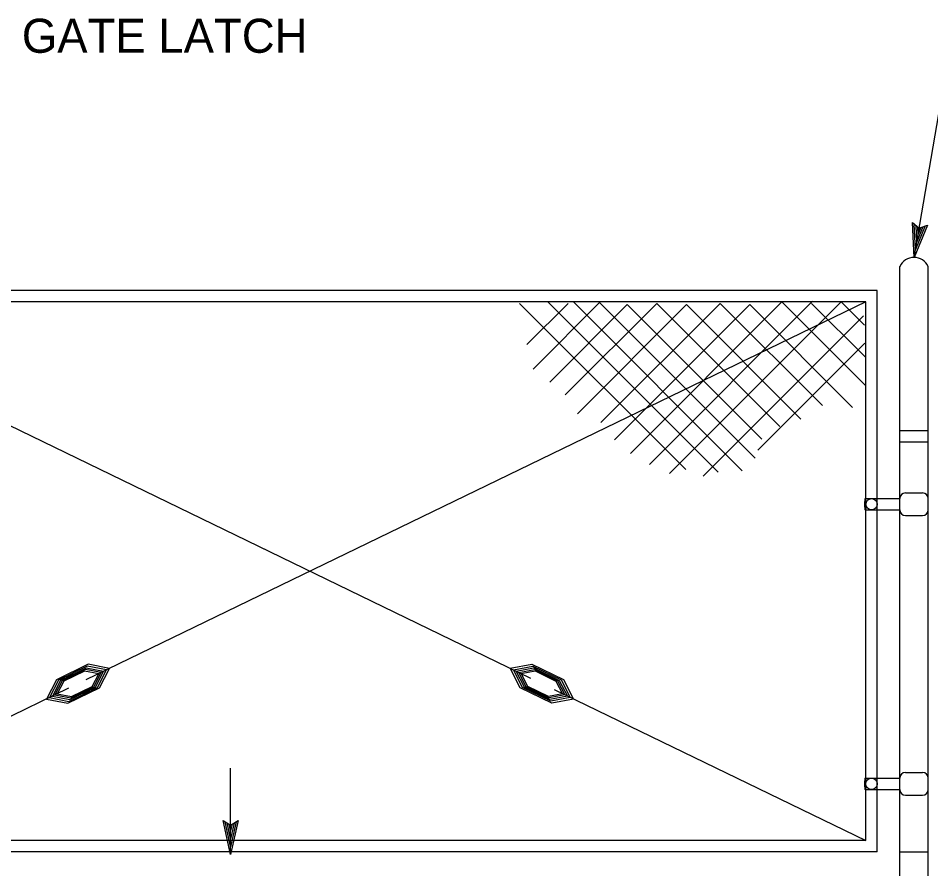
# Model space of a CAD drawing. Extents: x -121875 to -117742, y -103854 to -101122.
# Drawn here: x -120907.1 to -120746.2, y -102378.2 to -102228.3 of the extents above; entities that cross this region are included whole.
import ezdxf

# ---------------------------------------------------------------- set-up
doc = ezdxf.new("R2010")
doc.units = 0
for name, color, linetype in [('G-MARK', 7, 'Continuous'), ('G-TEXT', 7, 'Continuous'), ('Misc CnstDet(22)', 7, 'Continuous'), ('Nongeo Data(60)', 7, 'Continuous')]:
    doc.layers.add(name, color=color, linetype=linetype)

msp = doc.modelspace()

# ---------------------------------------------------------------- linework, layer by layer
at = {"layer": 'G-MARK'}
for p, q in [((-120749.16, -102270.41), (-120749.44, -102264.27)), ((-120749.44, -102264.27), (-120749.44, -102264.27)), ((-120749.44, -102264.27), (-120748.27, -102265.28)), ((-120746.81, -102264.72), (-120749.16, -102270.41)), ((-120748.92, -102269.03), (-120749.13, -102264.56)), ((-120747.2, -102264.88), (-120748.92, -102269.05)), ((-120748.68, -102267.68), (-120748.81, -102264.79)), ((-120747.59, -102265.04), (-120748.68, -102267.68)), ((-120748.44, -102266.32), (-120748.5, -102265.09)), ((-120747.96, -102265.16), (-120748.44, -102266.32)), ((-120748.27, -102265.28), (-120746.81, -102264.72)), ((-120746.81, -102264.72), (-120746.81, -102264.72)), ((-120749.16, -102270.41), (-120749.16, -102270.41)), ((-120869.67, -102375.7), (-120869.67, -102360.47))]:
    msp.add_line(p, q, dxfattribs=at)
msp.add_lwpolyline([(-120749.16, -102270.41), (-120744.76, -102245.1), (-120744.76, -102245.1)], dxfattribs=at)
at = {"layer": 'G-TEXT'}
for p, q in [((-120869.67, -102375.7), (-120871, -102369.7)), ((-120871, -102369.7), (-120871, -102369.7)), ((-120871, -102369.7), (-120869.67, -102370.5)), ((-120869.67, -102374.31), (-120870.64, -102369.93)), ((-120869.67, -102372.94), (-120870.29, -102370.11)), ((-120869.67, -102371.55), (-120869.93, -102370.35)), ((-120869.67, -102370.5), (-120868.33, -102369.7)), ((-120868.33, -102369.7), (-120869.67, -102375.7)), ((-120868.68, -102369.92), (-120869.67, -102374.32)), ((-120869.04, -102370.15), (-120869.67, -102372.94)), ((-120869.39, -102370.33), (-120869.67, -102371.55)), ((-120868.33, -102369.7), (-120868.33, -102369.7)), ((-120869.67, -102375.7), (-120869.67, -102375.7))]:
    msp.add_line(p, q, dxfattribs=at)
at = {"layer": 'Nongeo Data(60)'}
for p, q in [((-120751.66, -102358.97), (-120751.66, -102272.05)), ((-120746.66, -102358.97), (-120746.66, -102272.05)), ((-120755.66, -102276.24), (-120955.66, -102276.24)), ((-120755.66, -102301.58), (-120755.66, -102276.24)), ((-120757.66, -102278.24), (-120953.66, -102278.24)), ((-120953.66, -102278.24), (-120816.78, -102344.59)), ((-120757.66, -102278.24), (-120895.22, -102344.92)), ((-120789.41, -102307.83), (-120818.73, -102278.52)), ((-120817.42, -102285.75), (-120810.18, -102278.52)), ((-120816.35, -102290.14), (-120804.49, -102278.28)), ((-120783.72, -102308.3), (-120813.74, -102278.28)), ((-120813.39, -102292.4), (-120799.74, -102278.75)), ((-120810.66, -102294.65), (-120794.52, -102278.52)), ((-120779.45, -102308.06), (-120809.23, -102278.28)), ((-120808.52, -102297.98), (-120789.3, -102278.75)), ((-120777.19, -102305.81), (-120804.72, -102278.28)), ((-120804.37, -102299.52), (-120783.36, -102278.52)), ((-120801.99, -102302.6), (-120778.14, -102278.75)), ((-120776.01, -102302.49), (-120799.74, -102278.75)), ((-120799.15, -102304.98), (-120772.45, -102278.28)), ((-120795.81, -102306.91), (-120767.06, -102278.16)), ((-120772.8, -102300.23), (-120794.52, -102278.52)), ((-120792.26, -102308.54), (-120762, -102278.28)), ((-120769.12, -102298.93), (-120789.3, -102278.75)), ((-120765.33, -102296.55), (-120783.36, -102278.52)), ((-120759.99, -102296.91), (-120778.14, -102278.75)), ((-120757.79, -102292.93), (-120772.45, -102278.28)), ((-120757.66, -102288.08), (-120767.22, -102278.52)), ((-120757.9, -102282.38), (-120762, -102278.28)), ((-120757.66, -102301.21), (-120757.66, -102278.24)), ((-120786.33, -102309.01), (-120758.05, -102280.74)), ((-120776.72, -102304.38), (-120757.86, -102285.53)), ((-120757.66, -102373.24), (-120757.66, -102301.21)), ((-120751.66, -102300.95), (-120746.66, -102300.95)), ((-120755.66, -102375.24), (-120755.66, -102301.58)), ((-120751.66, -102302.95), (-120746.66, -102302.95)), ((-120755.66, -102312.95), (-120755.66, -102309.67)), ((-120751.66, -102311.93), (-120751.66, -102309.67)), ((-120746.66, -102311.94), (-120746.66, -102309.67)), ((-120751.66, -102317.59), (-120751.66, -102311.93)), ((-120750.66, -102311.95), (-120747.66, -102311.95)), ((-120746.66, -102317.59), (-120746.66, -102311.9)), ((-120757.78, -102312.95), (-120751.66, -102312.95)), ((-120751.66, -102314.95), (-120751.66, -102312.95)), ((-120746.66, -102314.95), (-120746.66, -102312.95)), ((-120757.78, -102314.95), (-120751.66, -102314.95)), ((-120755.66, -102317.59), (-120755.66, -102314.95)), ((-120750.66, -102315.95), (-120747.66, -102315.95)), ((-120894.81, -102342.16), (-120900.38, -102344.87)), ((-120894.99, -102342.51), (-120900, -102344.94)), ((-120895.15, -102342.82), (-120899.66, -102345.01)), ((-120895.29, -102343.09), (-120899.36, -102345.07)), ((-120892.53, -102343.62), (-120895.29, -102343.09)), ((-120892.07, -102343.4), (-120895.15, -102342.82)), ((-120891.57, -102343.16), (-120894.99, -102342.51)), ((-120891.01, -102342.89), (-120894.81, -102342.16)), ((-120893.17, -102346.25), (-120891.57, -102343.16)), ((-120892.79, -102346.32), (-120891.01, -102342.89)), ((-120820.37, -102342.86), (-120816.57, -102342.13)), ((-120818.59, -102346.29), (-120820.37, -102342.86)), ((-120819.81, -102343.14), (-120816.4, -102342.48)), ((-120818.22, -102346.23), (-120819.81, -102343.14)), ((-120819.31, -102343.38), (-120816.24, -102342.8)), ((-120818.86, -102343.61), (-120816.09, -102343.08)), ((-120816.57, -102342.13), (-120811, -102344.85)), ((-120816.4, -102342.48), (-120811.38, -102344.92)), ((-120816.24, -102342.8), (-120811.72, -102344.99)), ((-120816.09, -102343.08), (-120812.03, -102345.06)), ((-120895.42, -102343.35), (-120899.08, -102345.12)), ((-120892.93, -102343.82), (-120895.42, -102343.35)), ((-120894.1, -102346.07), (-120892.93, -102343.82)), ((-120893.82, -102346.12), (-120892.53, -102343.62)), ((-120893.51, -102346.18), (-120892.07, -102343.4)), ((-120817.87, -102346.17), (-120819.31, -102343.38)), ((-120817.57, -102346.11), (-120818.86, -102343.61)), ((-120818.45, -102343.81), (-120815.96, -102343.34)), ((-120817.29, -102346.06), (-120818.45, -102343.81)), ((-120815.96, -102343.34), (-120812.3, -102345.11)), ((-120811, -102344.85), (-120809.22, -102348.28)), ((-120898.24, -102346.39), (-120953.66, -102373.24)), ((-120900.38, -102344.87), (-120902.16, -102348.31)), ((-120900, -102344.94), (-120901.6, -102348.04)), ((-120899.66, -102345.01), (-120901.1, -102347.79)), ((-120899.36, -102345.07), (-120900.65, -102347.57)), ((-120899.08, -102345.12), (-120900.25, -102347.38)), ((-120898.36, -102349.03), (-120892.79, -102346.32)), ((-120898.19, -102348.69), (-120893.17, -102346.25)), ((-120898.03, -102348.38), (-120893.51, -102346.18)), ((-120897.88, -102348.1), (-120893.82, -102346.12)), ((-120897.76, -102347.85), (-120894.1, -102346.07)), ((-120813.02, -102349), (-120818.59, -102346.29)), ((-120813.2, -102348.66), (-120818.22, -102346.23)), ((-120813.36, -102348.36), (-120817.87, -102346.17)), ((-120813.5, -102348.09), (-120817.57, -102346.11)), ((-120813.63, -102347.84), (-120817.29, -102346.06)), ((-120812.3, -102345.11), (-120811.14, -102347.37)), ((-120812.03, -102345.06), (-120810.73, -102347.56)), ((-120811.72, -102344.99), (-120810.28, -102347.78)), ((-120811.38, -102344.92), (-120809.78, -102348.01)), ((-120901.6, -102348.04), (-120898.19, -102348.69)), ((-120901.1, -102347.79), (-120898.03, -102348.38)), ((-120900.65, -102347.57), (-120897.88, -102348.1)), ((-120900.25, -102347.38), (-120897.76, -102347.85)), ((-120811.14, -102347.37), (-120813.63, -102347.84)), ((-120810.73, -102347.56), (-120813.5, -102348.09)), ((-120810.28, -102347.78), (-120813.36, -102348.36)), ((-120809.78, -102348.01), (-120813.2, -102348.66)), ((-120812.61, -102346.61), (-120757.66, -102373.24)), ((-120902.16, -102348.31), (-120898.36, -102349.03)), ((-120809.22, -102348.28), (-120813.02, -102349)), ((-120751.66, -102361.22), (-120751.66, -102358.97)), ((-120751.66, -102366.89), (-120751.66, -102358.97)), ((-120746.66, -102361.24), (-120746.66, -102358.97)), ((-120746.66, -102366.89), (-120746.66, -102358.97)), ((-120757.78, -102362.24), (-120751.77, -102362.24)), ((-120751.66, -102366.89), (-120751.66, -102361.22)), ((-120751.66, -102364.24), (-120751.66, -102362.24)), ((-120750.66, -102361.24), (-120747.66, -102361.24)), ((-120746.66, -102366.89), (-120746.66, -102361.19)), ((-120746.66, -102364.24), (-120746.66, -102362.24)), ((-120757.78, -102364.24), (-120751.66, -102364.24)), ((-120750.66, -102365.24), (-120747.66, -102365.24)), ((-120751.66, -102426.24), (-120751.66, -102366.89)), ((-120746.66, -102426.24), (-120746.66, -102366.89)), ((-120757.66, -102373.24), (-120953.66, -102373.24)), ((-120755.66, -102375.24), (-120955.66, -102375.24)), ((-120751.66, -102375.24), (-120746.66, -102375.24))]:
    msp.add_line(p, q, dxfattribs=at)
for centre in [(-120756.65, -102313.95), (-120756.66, -102363.24)]:
    msp.add_circle(centre, 1, dxfattribs=at)
for centre, radius, start, end in [((-120749.16, -102273.13), 2.72, 23.2888, 156.7112), ((-120750.66, -102312.95), 1, 90, 180), ((-120747.66, -102312.95), 1, 0, 90), ((-120750.66, -102314.95), 1, 180, 270), ((-120747.66, -102314.95), 1, 270, 0), ((-120750.66, -102362.24), 1, 90, 180), ((-120747.66, -102362.24), 1, 0, 90), ((-120750.66, -102364.24), 1, 180, 270), ((-120747.66, -102364.24), 1, 270, 0)]:
    msp.add_arc(centre, radius, start, end, dxfattribs=at)
for centre in [(-120757.78, -102313.95), (-120757.78, -102363.24)]:
    msp.add_ellipse(centre, major_axis=(0, -1), ratio=0.098201, start_param=3.141593, end_param=6.283185, dxfattribs=at)

# ---------------------------------------------------------------- texts
at = {"layer": 'Misc CnstDet(22)'}
msp.add_text('GATE LATCH', height=6, dxfattribs=at).set_placement((-120906.49, -102234.34))

doc.saveas('drawing.dxf')
